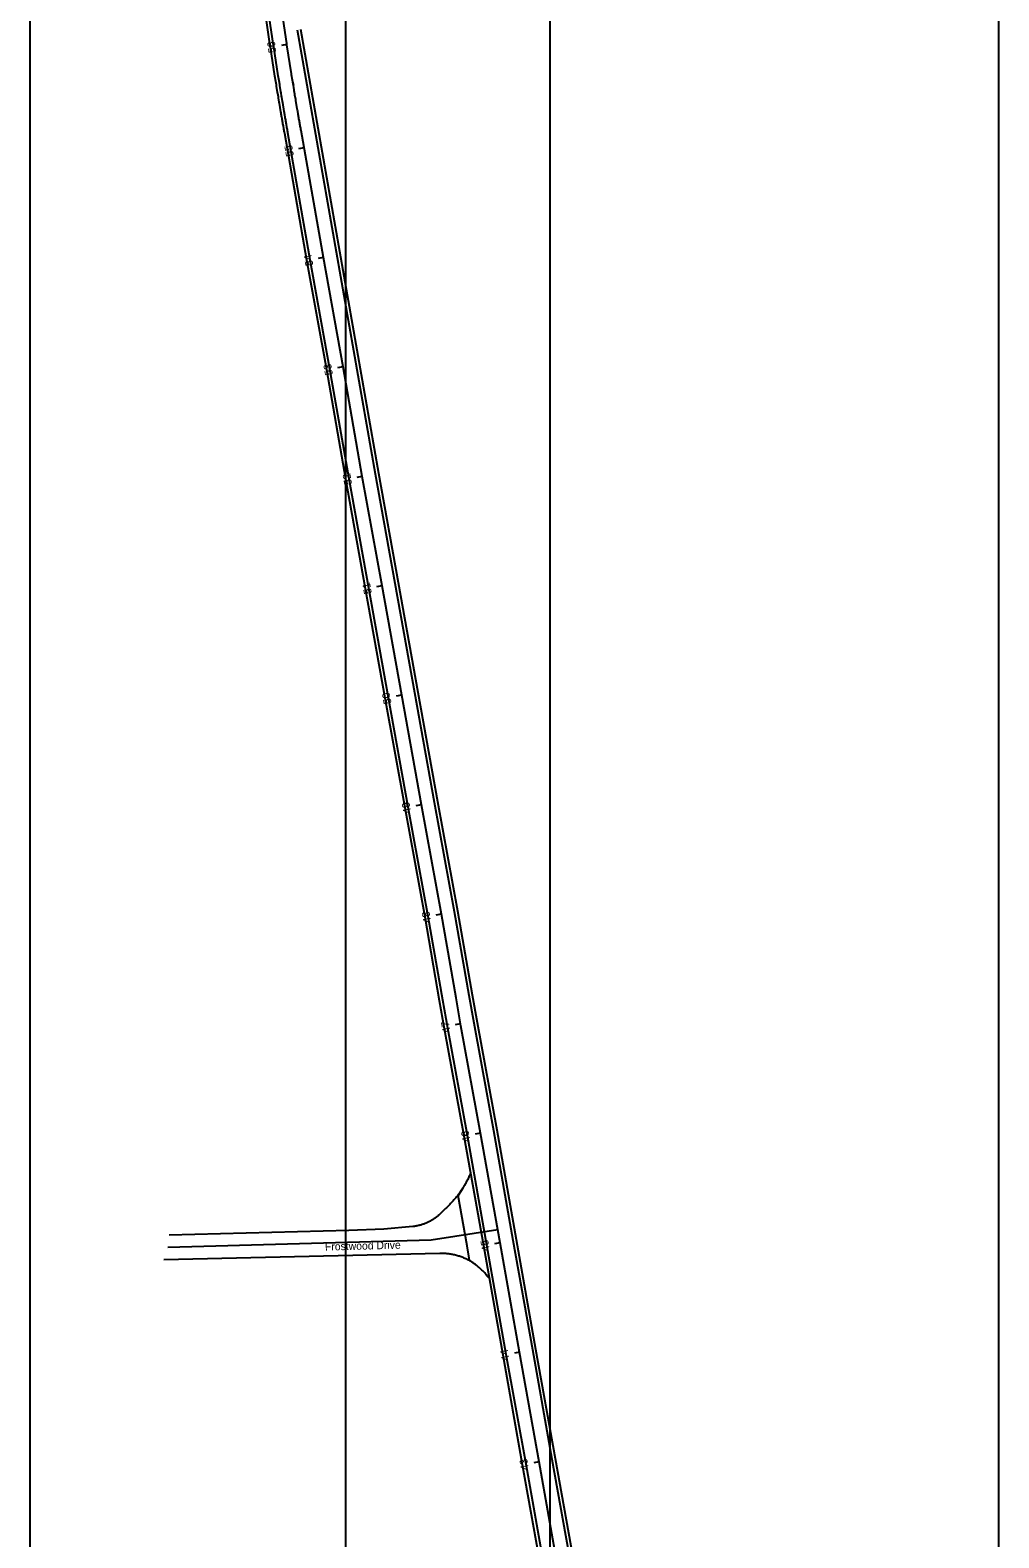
# Model space of a CAD drawing. Extents: x 2318076 to 2324211, y 613525 to 630327.
# Drawn here: x 2318413 to 2319284, y 619161 to 620517 of the extents above; entities that cross this region are included whole.
import ezdxf

# ---------------------------------------------------------------- set-up
doc = ezdxf.new("R2010")
doc.units = 0
for name, color, linetype in [('GE_P_CL_50', 7, 'Continuous'), ('GE_X_CL_50', 7, 'Continuous'), ('PV_P_EOP', 7, 'Continuous'), ('PV_P_Shoulder', 7, 'Continuous'), ('RS_Raster1', 7, 'Continuous'), ('SC_Scratch3', 7, 'Continuous')]:
    doc.layers.add(name, color=color, linetype=linetype)

msp = doc.modelspace()

# ---------------------------------------------------------------- linework, layer by layer
at = {"layer": 'GE_P_CL_50'}
for p, q in [((2318643.6, 620503.8), (2318638.7, 620503.1)), ((2318659.1, 620411), (2318654.2, 620410.1)), ((2318676.6, 620312.5), (2318671.7, 620311.6)), ((2318694.2, 620214.1), (2318689.3, 620213.2)), ((2318711.5, 620115.6), (2318706.6, 620114.7)), ((2318729.3, 620017.2), (2318724.4, 620016.3)), ((2318746.9, 619918.8), (2318742, 619917.9)), ((2318764.6, 619820.3), (2318759.7, 619819.4)), ((2318782.6, 619722), (2318777.7, 619721.1)), ((2318799.9, 619623.5), (2318795, 619622.6)), ((2318817.9, 619525.1), (2318813, 619524.2)), ((2318835.5, 619426.7), (2318830.5, 619425.8)), ((2318853.2, 619328.2), (2318848.3, 619327.3)), ((2318870.6, 619229.8), (2318865.7, 619228.9))]:
    msp.add_line(p, q, dxfattribs=at)
msp.add_lwpolyline([(2318888, 619131.3), (2318870.5, 619229.8), (2318852.9, 619328.2), (2318835.5, 619426.7), (2318817.9, 619525.1), (2318800.2, 619621.8), (2318795.8, 619646.7), (2318782.6, 619722), (2318764.6, 619820.3), (2318746.9, 619918.8), (2318729.3, 620017.2), (2318711.5, 620115.6), (2318694.2, 620214.1), (2318676.5, 620312.5), (2318656.4, 620426.6), (2318656.2, 620427.6), (2318656.1, 620428.6), (2318655.9, 620429.5), (2318655.7, 620430.5), (2318655.6, 620431.4), (2318655.4, 620432.4), (2318655.2, 620433.4), (2318655.1, 620434.3), (2318654.9, 620435.3), (2318654.7, 620436.2), (2318654.5, 620437.2), (2318654.4, 620438.2), (2318654.2, 620439.1), (2318654, 620440.1), (2318653.9, 620441.1), (2318653.7, 620442), (2318653.5, 620443), (2318653.4, 620443.9), (2318653.2, 620444.9), (2318653, 620445.9), (2318651.7, 620453.6), (2318651.6, 620454.5), (2318650.9, 620458.4), (2318650.8, 620459.3), (2318650.3, 620462.2), (2318650.1, 620463.2), (2318649.2, 620469), (2318649, 620469.9), (2318649.3, 620468), (2318649.5, 620467), (2318647.9, 620476.7), (2318647.7, 620477.6), (2318643.7, 620503.7), (2318643.5, 620504.7), (2318636.8, 620551)], dxfattribs=at)
at = {"layer": 'GE_X_CL_50'}
msp.add_lwpolyline([(2318536.7, 619422.6), (2318773.4, 619429.3), (2318833.3, 619438.5)], dxfattribs=at)
at = {"layer": 'PV_P_EOP'}
for points in [[(2318876.2, 619129.2), (2318858.7, 619227.7), (2318841, 619326.1), (2318823.6, 619424.6), (2318806.1, 619523), (2318788.4, 619619.6), (2318784, 619644.6), (2318770.8, 619719.9), (2318752.8, 619818.2), (2318735.1, 619916.6), (2318717.5, 620015.1), (2318699.7, 620113.5), (2318682.4, 620212), (2318664.7, 620310.4), (2318644.6, 620424.5), (2318644.4, 620425.5), (2318644.3, 620426.4), (2318644.1, 620427.4), (2318643.9, 620428.4), (2318643.7, 620429.3), (2318643.6, 620430.3), (2318643.4, 620431.3), (2318643.2, 620432.2), (2318643.1, 620433.2), (2318642.9, 620434.2), (2318642.7, 620435.1), (2318642.6, 620436.1), (2318642.4, 620437.1), (2318642.2, 620438), (2318642.1, 620439), (2318641.9, 620440), (2318641.7, 620440.9), (2318641.6, 620441.9), (2318641.4, 620442.9), (2318641.2, 620443.8), (2318639.9, 620451.6), (2318639.7, 620452.5), (2318639.1, 620456.4), (2318638.9, 620457.4), (2318638.4, 620460.3), (2318638.3, 620461.2), (2318637.3, 620467), (2318637.2, 620468), (2318636.6, 620471.2), (2318635.9, 620475.8), (2318631.8, 620501.9), (2318631.6, 620502.9), (2318624.9, 620549.4)], [(2318899.8, 619133.4), (2318882.3, 619231.9), (2318864.7, 619330.3), (2318847.3, 619428.8), (2318829.7, 619527.2), (2318812.1, 619623.9), (2318807.6, 619648.8), (2318794.4, 619724.1), (2318776.5, 619822.5), (2318758.8, 619920.9), (2318741.1, 620019.3), (2318723.4, 620117.7), (2318653.3, 620516.8)], [(2318809, 619489.6), (2318808.9, 619489.2), (2318808.5, 619488.4), (2318808.2, 619487.6), (2318807.8, 619486.7), (2318807.4, 619485.9), (2318807, 619485.1), (2318806.7, 619484.3), (2318806.3, 619483.5), (2318805.9, 619482.7), (2318805.4, 619481.9), (2318805, 619481.2), (2318804.6, 619480.4), (2318804.2, 619479.6), (2318803.7, 619478.8), (2318803.3, 619478.1), (2318802.8, 619477.3), (2318802.3, 619476.5), (2318801.9, 619475.8), (2318797.6, 619469.2)], [(2318808, 619411.1), (2318805.7, 619424), (2318797.6, 619469.2)], [(2318825.9, 619394.4), (2318824.4, 619396), (2318823.9, 619396.7), (2318823.3, 619397.4), (2318822.8, 619398.1), (2318822.2, 619398.8), (2318821.6, 619399.5), (2318821, 619400.2), (2318820.4, 619400.8), (2318819.8, 619401.5), (2318819.1, 619402.1), (2318818.5, 619402.7), (2318817.9, 619403.3), (2318817.2, 619403.9), (2318816.5, 619404.5), (2318815.8, 619405.1), (2318815.2, 619405.6), (2318814.5, 619406.2), (2318808, 619411.1)]]:
    msp.add_lwpolyline(points, dxfattribs=at)
at = {"layer": 'PV_P_Shoulder'}
for points in [[(2318873.2, 619128.7), (2318855.7, 619227.1), (2318838.1, 619325.6), (2318820.7, 619424), (2318803.1, 619522.4), (2318785.5, 619619.1), (2318781, 619644.1), (2318767.9, 619719.3), (2318749.9, 619817.7), (2318732.2, 619916.1), (2318714.5, 620014.5), (2318696.8, 620113), (2318679.5, 620211.5), (2318661.7, 620309.9), (2318641.7, 620424), (2318641.5, 620425), (2318641.3, 620425.9), (2318641.1, 620426.9), (2318641, 620427.9), (2318640.8, 620428.8), (2318640.6, 620429.8), (2318640.5, 620430.8), (2318640.3, 620431.7), (2318640.1, 620432.7), (2318639.9, 620433.7), (2318639.8, 620434.6), (2318639.6, 620435.6), (2318639.4, 620436.6), (2318639.3, 620437.5), (2318639.1, 620438.5), (2318638.9, 620439.5), (2318638.8, 620440.4), (2318638.6, 620441.4), (2318638.4, 620442.4), (2318638.3, 620443.3), (2318636.9, 620451), (2318636.8, 620452), (2318636.1, 620455.9), (2318636, 620456.9), (2318635.5, 620459.8), (2318635.3, 620460.7), (2318634.4, 620466.5), (2318634.2, 620467.5), (2318633.7, 620470.7), (2318632.9, 620475.3), (2318628.8, 620501.4), (2318628.7, 620502.5), (2318622, 620549)], [(2318902.8, 619133.9), (2318885.3, 619232.4), (2318867.6, 619330.8), (2318850.2, 619429.3), (2318832.7, 619527.8), (2318815, 619624.4), (2318810.6, 619649.3), (2318797.4, 619724.6), (2318779.4, 619823), (2318761.7, 619921.4), (2318744, 620019.8), (2318726.3, 620118.2), (2318656.3, 620517.3)]]:
    msp.add_lwpolyline(points, dxfattribs=at)
at = {"layer": 'RS_Raster1'}
for p, q in [((2318756.9, 619441.1), (2318730.8, 619438.8)), ((2318781.2, 619417), (2318532.9, 619411.4))]:
    msp.add_line(p, q, dxfattribs=at)
for points in [[(2318809, 619489.6), (2318808.9, 619489.2), (2318808.5, 619488.4), (2318808.2, 619487.6), (2318807.8, 619486.7), (2318807.4, 619485.9), (2318807, 619485.1), (2318806.7, 619484.3), (2318806.3, 619483.5), (2318805.9, 619482.7), (2318805.4, 619481.9), (2318805, 619481.2), (2318804.6, 619480.4), (2318804.2, 619479.6), (2318803.7, 619478.8), (2318803.3, 619478.1), (2318802.8, 619477.3), (2318802.3, 619476.5), (2318801.9, 619475.8), (2318801.4, 619475), (2318800.9, 619474.3), (2318800.4, 619473.5), (2318799.9, 619472.8), (2318799.4, 619472.1), (2318798.9, 619471.3), (2318798.4, 619470.6), (2318797.8, 619469.9), (2318797.3, 619469.2), (2318796.7, 619468.5), (2318796.2, 619467.8), (2318795.6, 619467.1), (2318795.1, 619466.4), (2318794.5, 619465.7), (2318793.9, 619465.1), (2318793.3, 619464.4), (2318792.7, 619463.7), (2318792.1, 619463.1), (2318791.5, 619462.4), (2318790.9, 619461.8), (2318790.3, 619461.1), (2318789.6, 619460.5), (2318789, 619459.9), (2318788.4, 619459.3), (2318787.7, 619458.6), (2318787.1, 619458), (2318786.4, 619457.4), (2318785.8, 619456.8), (2318785.1, 619456.3), (2318784.4, 619455.7)], [(2318784.4, 619455.7), (2318783.9, 619455.1), (2318783.5, 619454.6), (2318783, 619454.1), (2318782.5, 619453.5), (2318781.9, 619453), (2318781.4, 619452.5), (2318780.9, 619452), (2318780.4, 619451.5), (2318779.8, 619451), (2318779.3, 619450.6), (2318778.7, 619450.1), (2318778.1, 619449.7), (2318777.6, 619449.2), (2318777, 619448.8), (2318776.4, 619448.4), (2318775.8, 619448), (2318775.2, 619447.6), (2318774.6, 619447.2), (2318773.9, 619446.8), (2318773.3, 619446.5), (2318772.7, 619446.1), (2318772, 619445.8), (2318771.4, 619445.4), (2318770.7, 619445.1), (2318770.1, 619444.8), (2318769.4, 619444.5), (2318768.8, 619444.2), (2318768.1, 619443.9), (2318767.4, 619443.7), (2318766.7, 619443.4), (2318766.1, 619443.2), (2318765.4, 619442.9), (2318764.7, 619442.7), (2318764, 619442.5), (2318763.3, 619442.3), (2318762.6, 619442.1), (2318761.9, 619442), (2318761.2, 619441.8), (2318760.5, 619441.7), (2318759.8, 619441.5), (2318759, 619441.4), (2318758.3, 619441.3), (2318757.6, 619441.2), (2318756.9, 619441.1)], [(2318730.8, 619438.8), (2318699.3, 619437.7), (2318537.7, 619433.6)], [(2318825.9, 619394.4), (2318824.4, 619396), (2318823.9, 619396.7), (2318823.3, 619397.4), (2318822.8, 619398.1), (2318822.2, 619398.8), (2318821.6, 619399.5), (2318821, 619400.2), (2318820.4, 619400.8), (2318819.8, 619401.5), (2318819.1, 619402.1), (2318818.5, 619402.7), (2318817.9, 619403.3), (2318817.2, 619403.9), (2318816.5, 619404.5), (2318815.8, 619405.1), (2318815.2, 619405.6), (2318814.5, 619406.2), (2318813.7, 619406.7), (2318813, 619407.3), (2318812.3, 619407.8), (2318811.6, 619408.3), (2318810.8, 619408.8), (2318810.1, 619409.2), (2318809.3, 619409.7), (2318808.5, 619410.1), (2318807.8, 619410.6), (2318807, 619411), (2318806.2, 619411.4), (2318805.4, 619411.8), (2318804.6, 619412.2), (2318803.8, 619412.6), (2318802.9, 619412.9), (2318802.1, 619413.3), (2318801.3, 619413.6), (2318800.5, 619413.9), (2318799.6, 619414.2), (2318798.8, 619414.5), (2318797.9, 619414.7), (2318797.1, 619415), (2318796.2, 619415.2), (2318795.3, 619415.5), (2318794.5, 619415.7), (2318793.6, 619415.9), (2318792.7, 619416), (2318791.9, 619416.2), (2318791, 619416.4), (2318790.1, 619416.5), (2318789.2, 619416.6), (2318788.3, 619416.7), (2318787.4, 619416.8), (2318786.6, 619416.9), (2318785.7, 619416.9), (2318784.8, 619417), (2318783.9, 619417), (2318783, 619417), (2318782.1, 619417), (2318781.2, 619417)]]:
    msp.add_lwpolyline(points, dxfattribs=at)
at = {"layer": 'SC_Scratch3'}
for p, q in [((2318412.8, 614778.4), (2318412.8, 630327.2)), ((2318696.7, 614778.4), (2318696.7, 630327.2)), ((2318880.5, 614778.4), (2318880.5, 630327.2)), ((2319283.9, 614778.4), (2319283.9, 630327.2))]:
    msp.add_line(p, q, dxfattribs=at)

# ---------------------------------------------------------------- texts
at = {"layer": 'GE_P_CL_50'}
for s, rotation, p in [('56', 98.664, (2318634.3, 620496.8)), ('55', 99.8658, (2318650, 620403.8)), ('54', 100.3286, (2318667.5, 620305.4)), ('53', 99.7541, (2318685.1, 620207)), ('52', 100.2644, (2318702.4, 620108.5)), ('51', 100.1654, (2318720.1, 620010.4)), ('50', 100.1542, (2318737.8, 619911.5)), ('49', 100.3914, (2318755.6, 619813.1)), ('48', 99.9262, (2318773.5, 619714.7)), ('47', 100.1064, (2318790.9, 619616)), ('46', 100.7349, (2318808.9, 619517.7)), ('Frostwood Drive', 1.4386, (2318678, 619419.6)), ('45', 99.7749, (2318826.3, 619419.5)), ('44', 100.5044, (2318844.1, 619321.1)), ('43', 99.8567, (2318861.4, 619222.7))]:
    msp.add_text(s, height=7, rotation=rotation, dxfattribs=at).set_placement(p)

doc.saveas('drawing.dxf')
